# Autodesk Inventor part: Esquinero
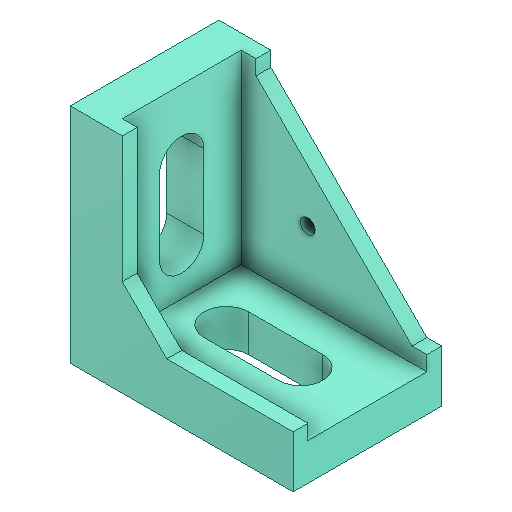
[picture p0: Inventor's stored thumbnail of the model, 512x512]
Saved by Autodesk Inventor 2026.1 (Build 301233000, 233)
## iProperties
Created: 2025-06
Part Number: Esquinero
Material: Genérico
Document SubType Name: Modeling
Designer: piero
Density: 1 g/cm^3
Appearance: Suave - Turquesa
Author: piero
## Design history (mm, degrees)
sketch "Boceto1"
  geometry: L1 (0, 0)-(30, 0); L2 (30, 0)-(30, -20); L3 (30, -20)-(0, -20); L4 (0, -20)-(0, 0); L5 (21, -10)-(11, -10); L6 (21, -7)-(11, -7); L7 (11, -13)-(21, -13); A1 r 3 centre (21, -10) between (21, -13) and (21, -7); A2 r 3 centre (11, -10) between (11, -7) and (11, -13); 5 further points
  constraints: 16 end point, 6 point on circle, 4 tangent, 3 midpoint, 3 parallel, 2 centre point, 2 horizontal, 1 perpendicular
  dimensions: "d0" = 30 distance of L2.end L3.end; "d1" = 20 distance of L1.end L2.end; "d2" = 10 distance of L5.start L5.end; "d3" = 6 diameter of A2; "d4" = 6 distance of point (24, -10) point (30, -10)
extrude "Extrusión1" new body sketch "Boceto1" distance "d6" = 5; taper "d7" = 0 deg
sketch "Boceto2"
  geometry: L1 (0, 0)-(20, 0) reference; L2 (0, 0)-(20, 0); L3 (20, 0)-(20, 5); L4 (20, 5)-(0, 5); L5 (0, 5)-(0, 0); 1 further point
  constraints: 8 end point, 2 parallel, 1 horizontal, 1 perpendicular
  dimensions: "d8" = 20 distance of L4.end L3.end; "d9" = 5 distance of L3.end L2.end
extrude "Extrusión2" join sketch "Boceto2" distance "d10" = 25; taper "d11" = 0 deg
sketch "Boceto3"
  geometry: L1 (6, 10)-(16, 10); L2 (6, 7)-(16, 7); L3 (16, 13)-(6, 13); L4 (25, 20)-(25, 0) reference; L5 (0, 0)-(25, 0) reference; A1 r 3 centre (6, 10) between (6, 13) and (6, 7); A2 r 3 centre (16, 10) between (16, 7) and (16, 13); 4 further points
  constraints: 8 end point, 5 point on circle, 4 tangent, 2 centre point, 2 midpoint, 1 horizontal, 1 parallel
  dimensions: "d12" = 10 distance of L1.start L1.end; "d13" = 6 diameter of A2; "d14" = 6 distance of point (25, 10) point (19, 10); "d15" = 10 distance from line of L5 point (11, 10)
extrude "Extrusión3" cut sketch "Boceto3" distance "d16" = 5; taper "d17" = 0 deg
sketch "Boceto4"
  geometry: L1 (5, 30)-(5, 5) reference; L2 (5, 5)-(30, 5) reference; L3 (5, 5)-(5, 28); L4 (5, 30)-(7, 30); L5 (7, 30)-(7, 28); L6 (30, 5)-(30, 7); L7 (30, 7)-(28, 7); L8 (28, 7)-(7, 28); 2 further points
  constraints: 12 end point, 3 perpendicular, 2 point on line, 1 horizontal, 1 vertical
  dimensions: "d18" = 2 distance of L3.end L1.start; "d19" = 2 distance of point (28, 5) L2.end; "d22" = 2 distance of L2.end L6.end
extrude "Extrusión4" join sketch "Boceto4" distance "d20" = 2; taper "d21" = 0 deg
sketch "Boceto5"
  geometry: L1 (-30, 0)-(-30, 5) reference; L2 (-30, 0)-(-30, 7) reference; L3 (-30, 5)-(-30, 7); L4 (-30, 7)-(-28, 7); L5 (-7, 30)-(-7, 28) reference; L6 (-28, 7)-(-7, 28); L7 (-7, 28)-(-7, 30); L8 (-7, 30)-(-5, 30); L9 (-5, 30)-(-5, 5); L10 (-5, 5)-(-30, 5); 1 further point
  constraints: 14 end point, 4 perpendicular, 1 collinear, 1 point on line, 1 vertical
  dimensions: "d23" = 2 distance of L2.end L4.end
extrude "Extrusión5" join sketch "Boceto5" distance "d24" = 2; taper "d25" = 0 deg
sketch "Boceto6"
  geometry: L1 (28, 7)-(7, 28) reference; L2 (7, 28)-(7, 13); L3 (7, 13)-(13, 7); L4 (13, 7)-(28, 7); 1 further point
  constraints: 6 end point, 1 perpendicular, 1 vertical
  dimensions: "d26" = 45 deg angle of L4 L3; "d27" = 15 distance of L3.end L1.start
extrude "Extrusión6" cut sketch "Boceto6" distance "d28" = 2; taper "d29" = 0 deg
sketch "Boceto7"
  geometry: L1 (7, 28)-(28, 7) reference; L2 (7, 28)-(7, 7); L3 (7, 7)-(28, 7); L4 (7, 7)-(17.5, 17.5); L5 (28, 7)-(7, 28) reference; 3 further points
  constraints: 6 end point, 2 midpoint, 1 perpendicular, 1 point on line, 1 vertical
  dimensions: "d30" = 5 distance of point (17.5, 17.5) point (13.964, 13.964)
hole "Agujero1" sketch "Boceto7" at (13.964, 13.964) diameter "d31" = 2; stored, may be unused: countersink angle "d35" = 90 deg, drill point angle "d37" = 118 deg; dims "d32" = 6, "d33" = 4, "d34" = 2, "d36" = 8
node "Sólido1"
